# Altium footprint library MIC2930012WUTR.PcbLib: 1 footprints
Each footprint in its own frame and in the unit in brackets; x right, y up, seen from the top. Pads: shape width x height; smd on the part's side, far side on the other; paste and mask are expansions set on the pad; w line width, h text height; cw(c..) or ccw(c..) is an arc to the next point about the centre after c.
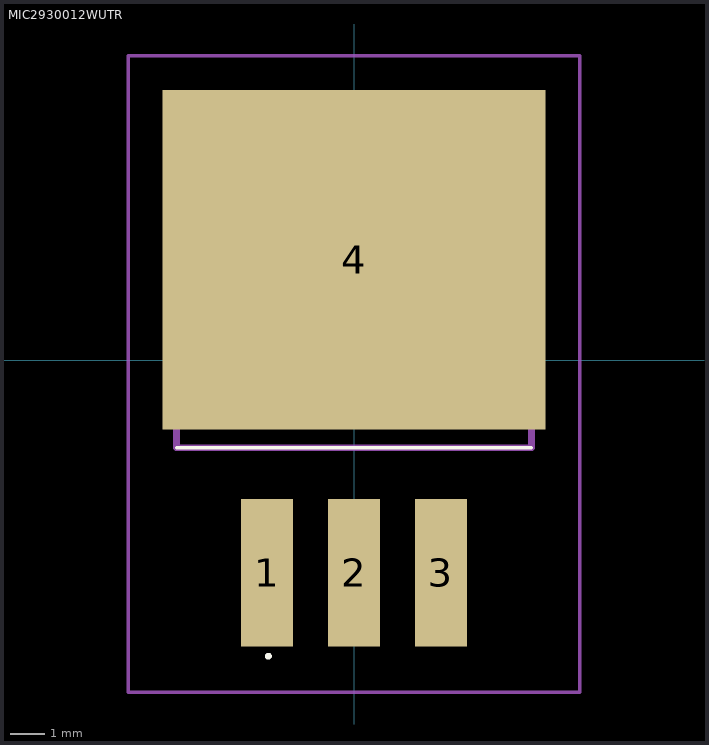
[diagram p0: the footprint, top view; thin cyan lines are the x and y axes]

## MIC2930012WUTR [mil]
pads (4):
  rect 60x170 smd: 1(-100,-244.61) 2(0,-244.61) 3(100,-244.61)
  rect 440x390 smd: 4(0,115.39)
Top Overlay:
  lines w3.94: -203.98,-100.87 203.98,-100.87 ; -98.43,-342.52 ccw(c-98.43,-340.55) -98.43,-338.58 ; -98.43,-342.52 -98.43,-342.52 ; -98.43,-342.52 cw(c-98.43,-340.55) -98.43,-338.58 ; -98.43,-338.58 -98.43,-338.58
Mechanical 15:
  lines w7.87: -203.98,-100.87 203.98,-100.87 203.98,244.61 -203.98,244.61 -203.98,-100.87
Mechanical 20:
  lines w3.94: -259.37,-381.89 259.37,-381.89 259.37,349.76 -259.37,349.76 -259.37,-381.89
